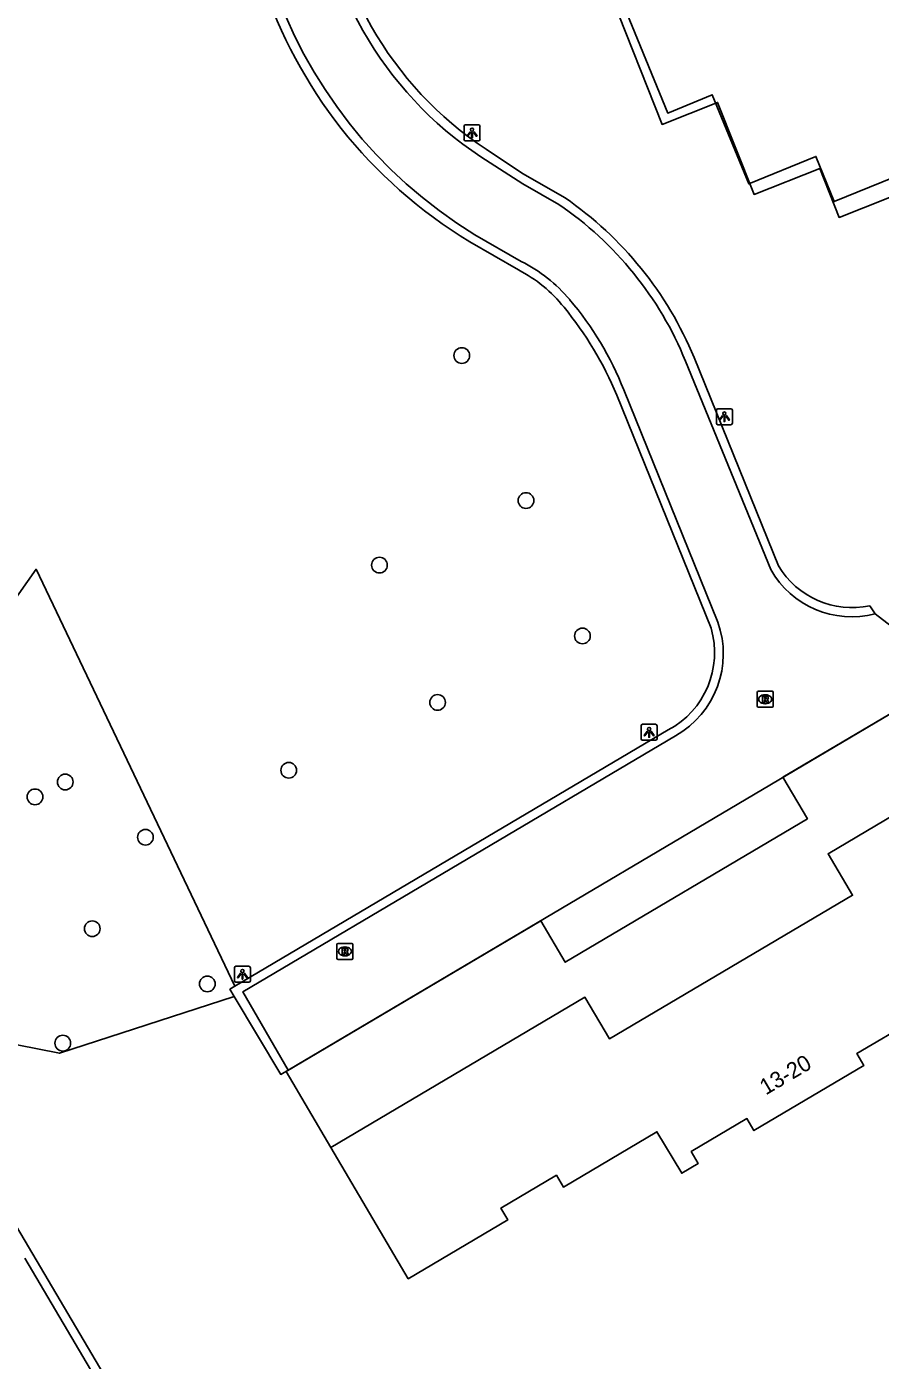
# Model space of a CAD drawing. Extents: x 156664 to 157568, y 383571 to 384421.
# Drawn here: x 156750.4 to 156803.6, y 383749.5 to 383832.6 of the extents above; entities that cross this region are included whole.
import ezdxf

# ---------------------------------------------------------------- set-up
doc = ezdxf.new("R2010")
doc.units = 0
for name, color, linetype in [('IMGEO_Boom', 7, 'Continuous'), ('IMGEO_Groenvoorziening', 7, 'Continuous'), ('IMGEO_Lichtpunt', 7, 'Continuous'), ('IMGEO_Pand', 7, 'Continuous'), ('IMGEO_Pand_nummerreeks', 7, 'Continuous'), ('IMGEO_Pand_overbouw', 7, 'Continuous'), ('IMGEO_Pand_vergunning_verleend', 7, 'Continuous'), ('IMGEO_Rijbaan_lokaal_gesloten', 7, 'Continuous'), ('IMGEO_Rijbaan_lokaal_halfverhard', 7, 'Continuous'), ('IMGEO_Rijbaan_lokaal_open', 7, 'Continuous'), ('IMGEO_Rioolput', 7, 'Continuous')]:
    doc.layers.add(name, color=color, linetype=linetype)

msp = doc.modelspace()

# ---------------------------------------------------------------- linework, layer by layer
at = {"layer": 'IMGEO_Boom'}
for centre in [(156777.531, 383812.095), (156781.531, 383803.065), (156772.399, 383799.045), (156785.049, 383794.635), (156776.021, 383790.495), (156766.747, 383786.271), (156752.817, 383785.542), (156750.932, 383784.616), (156757.815, 383782.1), (156754.501, 383776.407), (156761.671, 383772.969), (156752.666, 383769.281)]:
    msp.add_circle(centre, 0.489, dxfattribs=at)
at = {"layer": 'IMGEO_Groenvoorziening'}
msp.add_lwpolyline([(156763.35, 383772.193), (156752.452, 383768.65), (156744.519, 383770.221), (156737.487, 383779.603), (156751.004, 383798.789), (156763.392, 383772.822)], dxfattribs=at)
at = {"layer": 'IMGEO_Lichtpunt'}
for p, q in [((156777.668, 383826.364), (156777.668, 383825.557)), ((156777.668, 383826.364), (156777.668, 383825.557)), ((156778.57, 383826.459), (156777.762, 383826.459)), ((156778.57, 383826.459), (156777.762, 383826.459)), ((156778.664, 383825.557), (156778.664, 383826.364)), ((156778.664, 383825.557), (156778.664, 383826.364)), ((156777.762, 383825.463), (156778.57, 383825.463)), ((156777.762, 383825.463), (156778.57, 383825.463)), ((156793.395, 383808.688), (156793.395, 383807.881)), ((156793.395, 383808.688), (156793.395, 383807.881)), ((156794.297, 383808.783), (156793.489, 383808.783)), ((156794.297, 383808.783), (156793.489, 383808.783)), ((156794.391, 383807.881), (156794.391, 383808.688)), ((156794.391, 383807.881), (156794.391, 383808.688)), ((156793.489, 383807.787), (156794.297, 383807.787)), ((156793.489, 383807.787), (156794.297, 383807.787)), ((156788.705, 383789.038), (156788.705, 383788.231)), ((156788.705, 383789.038), (156788.705, 383788.231)), ((156789.607, 383789.133), (156788.799, 383789.133)), ((156789.607, 383789.133), (156788.799, 383789.133)), ((156789.701, 383788.231), (156789.701, 383789.038)), ((156789.701, 383788.231), (156789.701, 383789.038)), ((156788.799, 383788.137), (156789.607, 383788.137)), ((156788.799, 383788.137), (156789.607, 383788.137)), ((156763.359, 383773.974), (156763.359, 383773.167)), ((156763.359, 383773.974), (156763.359, 383773.167)), ((156764.261, 383774.069), (156763.453, 383774.069)), ((156764.261, 383774.069), (156763.453, 383774.069)), ((156764.355, 383773.167), (156764.355, 383773.974)), ((156764.355, 383773.167), (156764.355, 383773.974)), ((156763.453, 383773.073), (156764.261, 383773.073)), ((156763.453, 383773.073), (156764.261, 383773.073))]:
    msp.add_line(p, q, dxfattribs=at)
for points in [[(156778.042, 383826.028), (156778.081, 383826), (156777.893, 383825.738), (156777.855, 383825.765), (156778.042, 383826.028)], [(156778.144, 383825.98), (156778.191, 383825.98), (156778.191, 383825.658), (156778.144, 383825.658), (156778.144, 383825.98)], [(156778.254, 383826), (156778.292, 383826.027), (156778.479, 383825.765), (156778.44, 383825.737), (156778.254, 383826)], [(156793.769, 383808.352), (156793.808, 383808.324), (156793.62, 383808.062), (156793.582, 383808.089), (156793.769, 383808.352)], [(156793.871, 383808.304), (156793.918, 383808.304), (156793.918, 383807.982), (156793.871, 383807.982), (156793.871, 383808.304)], [(156793.981, 383808.324), (156794.019, 383808.351), (156794.206, 383808.089), (156794.167, 383808.061), (156793.981, 383808.324)], [(156789.079, 383788.702), (156789.118, 383788.674), (156788.93, 383788.412), (156788.892, 383788.439), (156789.079, 383788.702)], [(156789.181, 383788.654), (156789.228, 383788.654), (156789.228, 383788.332), (156789.181, 383788.332), (156789.181, 383788.654)], [(156789.291, 383788.674), (156789.329, 383788.701), (156789.516, 383788.439), (156789.477, 383788.411), (156789.291, 383788.674)], [(156763.733, 383773.638), (156763.772, 383773.61), (156763.584, 383773.348), (156763.546, 383773.375), (156763.733, 383773.638)], [(156763.835, 383773.59), (156763.882, 383773.59), (156763.882, 383773.268), (156763.835, 383773.268), (156763.835, 383773.59)], [(156763.945, 383773.61), (156763.983, 383773.637), (156764.17, 383773.375), (156764.131, 383773.347), (156763.945, 383773.61)]]:
    msp.add_lwpolyline(points, dxfattribs=at)
for centre in [(156778.167, 383826.162), (156793.894, 383808.486), (156789.204, 383788.836), (156763.858, 383773.772)]:
    msp.add_circle(centre, 0.0994, dxfattribs=at)
for centre, start, end in [((156777.762, 383826.364), 90, 180), ((156777.762, 383826.364), 90, 180), ((156778.57, 383826.364), 0, 90), ((156778.57, 383826.364), 0, 90), ((156777.762, 383825.557), 180, 270), ((156777.762, 383825.557), 180, 270), ((156778.57, 383825.557), 270, 0), ((156778.57, 383825.557), 270, 360), ((156793.489, 383808.688), 90, 180), ((156793.489, 383808.688), 90, 180), ((156794.297, 383808.688), 0, 90), ((156794.297, 383808.688), 0, 90), ((156793.489, 383807.881), 180, 270), ((156793.489, 383807.881), 180, 270), ((156794.297, 383807.881), 270, 0), ((156794.297, 383807.881), 270, 360), ((156788.799, 383789.038), 90, 180), ((156788.799, 383789.038), 90, 180), ((156789.607, 383789.038), 0, 90), ((156789.607, 383789.038), 0, 90), ((156788.799, 383788.231), 180, 270), ((156788.799, 383788.231), 180, 270), ((156789.607, 383788.231), 270, 0), ((156789.607, 383788.231), 270, 360), ((156763.453, 383773.974), 90, 180), ((156763.453, 383773.974), 90, 180), ((156764.261, 383773.974), 0, 90), ((156764.261, 383773.974), 0, 90), ((156763.453, 383773.167), 180, 270), ((156763.453, 383773.167), 180, 270), ((156764.261, 383773.167), 270, 0), ((156764.261, 383773.167), 270, 360)]:
    msp.add_arc(centre, 0.0946, start, end, dxfattribs=at)
at = {"layer": 'IMGEO_Pand'}
for points in [[(156807.966, 383825.04), (156808.116, 383824.67), (156800.741, 383821.682), (156799.598, 383824.496), (156795.415, 383822.785), (156793.137, 383828.33), (156790.362, 383827.188), (156787.627, 383833.862), (156788.459, 383834.206), (156786.933, 383837.925), (156786.103, 383837.581), (156783.375, 383844.241), (156784.761, 383844.813), (156780.2, 383855.943), (156794.056, 383861.612), (156795.923, 383862.376), (156798.209, 383863.311), (156804.039, 383865.696)], [(156805.608, 383770.675), (156802.142, 383768.636), (156802.59, 383767.89), (156795.733, 383763.84), (156795.294, 383764.582), (156791.83, 383762.532), (156792.267, 383761.792), (156791.238, 383761.184), (156789.694, 383763.767), (156783.863, 383760.324), (156783.43, 383761.054), (156779.966, 383759.014), (156780.395, 383758.276), (156774.198, 383754.617), (156769.377, 383762.774), (156785.206, 383772.136), (156786.73, 383769.552), (156801.885, 383778.489), (156800.361, 383781.074), (156811.074, 383787.411)]]:
    msp.add_lwpolyline(points, dxfattribs=at)
at = {"layer": 'IMGEO_Pand_overbouw'}
msp.add_lwpolyline([(156808.267, 383792.167), (156797.545, 383785.836), (156799.072, 383783.25), (156783.979, 383774.316), (156782.465, 383776.905), (156766.577, 383767.511), (156769.377, 383762.774), (156785.206, 383772.136), (156786.73, 383769.552), (156801.885, 383778.489), (156800.361, 383781.074), (156811.074, 383787.411)], close=True, dxfattribs=at)
at = {"layer": 'IMGEO_Pand_vergunning_verleend'}
msp.add_lwpolyline([(156780.469, 383854.207), (156810.422, 383866.069), (156813.706, 383857.943), (156816.747, 383859.147), (156823.563, 383841.936), (156820.432, 383840.696), (156822.305, 383835.967), (156820.454, 383835.234), (156822.799, 383829.314), (156801.042, 383820.698), (156799.834, 383823.747), (156795.744, 383822.127), (156793.475, 383827.857), (156790.011, 383826.485), (156783.663, 383842.517), (156784.904, 383843.008), (156780.469, 383854.207)], dxfattribs=at)
at = {"layer": 'IMGEO_Rijbaan_lokaal_gesloten'}
for points in [[(156783.963, 383821.909), (156781.318, 383823.436), (156779.043, 383824.936)], [(156778.718, 383824.465), (156781.34, 383822.787), (156783.574, 383821.503)], [(156781.058, 383817.423), (156778.021, 383819.184)], [(156778.347, 383819.615), (156781.238, 383817.955)], [(156791.468, 383811.752), (156796.785, 383798.775)], [(156797.264, 383799.006), (156792.007, 383811.962)], [(156787.626, 383809.956), (156793.479, 383795.501)], [(156793.061, 383795.116), (156787.182, 383809.636)], [(156803.286, 383796.013), (156802.956, 383796.509)], [(156763.392, 383772.822), (156790.393, 383788.783)], [(156790.845, 383788.423), (156763.879, 383772.471), (156766.719, 383767.595)], [(156763.392, 383772.822), (156763.084, 383772.64), (156763.35, 383772.193)], [(156766.719, 383767.595), (156766.247, 383767.332), (156763.35, 383772.193)]]:
    msp.add_lwpolyline(points, dxfattribs=at)
for centre, radius, start, end in [((156791.351, 383843.635), 22.958, 128.2084, 236.61447), ((156791.42, 383843.662), 22.447, 128.87084, 236.53772), ((156793.467, 383844.757), 29.876, 157.83284, 238.86903), ((156793.864, 383844.982), 29.736, 158.50885, 238.54582), ((156771.164, 383803.333), 22.559, 22.49043, 55.43354), ((156771.39, 383803.568), 21.682, 22.17535, 55.809), ((156777.125, 383809.711), 8.657, 38.49853, 62.97757), ((156776.877, 383809.328), 9.667, 40.26713, 63.18213), ((156767.174, 383801.336), 21.661, 22.53107, 39.45194), ((156768.931, 383802.558), 20.105, 21.58981, 40.3527), ((156801.831, 383801.62), 5.793, 209.41518, 284.54765), ((156801.864, 383801.756), 5.36, 210.87491, 281.75233), ((156787.836, 383793.589), 5.444, 298.01823, 16.29181), ((156787.98, 383793.518), 5.846, 299.34857, 19.82703)]:
    msp.add_arc(centre, radius, start, end, dxfattribs=at)
at = {"layer": 'IMGEO_Rijbaan_lokaal_halfverhard'}
msp.add_lwpolyline([(156734.042, 383784.492), (156785.456, 383697.466)], dxfattribs=at)
at = {"layer": 'IMGEO_Rijbaan_lokaal_open'}
for points in [[(156803.286, 383796.013), (156808.279, 383792.181), (156766.719, 383767.595)], [(156784.956, 383697.199), (156750.297, 383755.891)]]:
    msp.add_lwpolyline(points, dxfattribs=at)
at = {"layer": 'IMGEO_Rioolput'}
for p, q in [((156795.937, 383790.27), (156795.937, 383791.122)), ((156796.012, 383791.196), (156796.864, 383791.196)), ((156796.425, 383790.976), (156796.45, 383790.976)), ((156796.938, 383791.122), (156796.938, 383790.27)), ((156796.864, 383790.196), (156796.012, 383790.196)), ((156796.448, 383790.416), (156796.423, 383790.416)), ((156769.745, 383774.569), (156769.745, 383775.421)), ((156769.82, 383775.495), (156770.672, 383775.495)), ((156770.233, 383775.275), (156770.258, 383775.275)), ((156770.746, 383775.421), (156770.746, 383774.569)), ((156770.672, 383774.495), (156769.82, 383774.495)), ((156770.256, 383774.715), (156770.231, 383774.715))]:
    msp.add_line(p, q, dxfattribs=at)
for points in [[(156795.937, 383790.27), (156795.937, 383791.122)], [(156796.012, 383791.196), (156796.864, 383791.196)], [(156796.526, 383790.894), (156796.274, 383790.896), (156796.274, 383790.496)], [(156796.938, 383791.122), (156796.938, 383790.27)], [(156796.864, 383790.196), (156796.012, 383790.196)], [(156796.274, 383790.496), (156796.398, 383790.496), (156796.398, 383790.658), (156796.409, 383790.658)], [(156796.452, 383790.815), (156796.398, 383790.815), (156796.398, 383790.734)], [(156796.398, 383790.734), (156796.45, 383790.734)], [(156796.456, 383790.629), (156796.527, 383790.496), (156796.667, 383790.496), (156796.602, 383790.622)], [(156769.745, 383774.569), (156769.745, 383775.421)], [(156769.82, 383775.495), (156770.672, 383775.495)], [(156770.334, 383775.193), (156770.082, 383775.195), (156770.082, 383774.795)], [(156770.26, 383775.114), (156770.206, 383775.114), (156770.206, 383775.033)], [(156770.746, 383775.421), (156770.746, 383774.569)], [(156770.672, 383774.495), (156769.82, 383774.495)], [(156770.082, 383774.795), (156770.206, 383774.795), (156770.206, 383774.957), (156770.217, 383774.957)], [(156770.206, 383775.033), (156770.258, 383775.033)], [(156770.264, 383774.928), (156770.335, 383774.795), (156770.475, 383774.795), (156770.41, 383774.921)]]:
    msp.add_lwpolyline(points, dxfattribs=at)
for centre, radius, start, end in [((156796.014, 383791.12), 0.0765, 91.55205, 178.44795), ((156796.014, 383791.12), 0.0765, 91.55205, 178.44795), ((156796.525, 383790.784), 0.109, 350.36119, 89.41601), ((156796.862, 383791.12), 0.0765, 1.55205, 88.44795), ((156796.862, 383791.12), 0.0765, 1.55205, 88.44795), ((156796.014, 383790.272), 0.0765, 181.55205, 268.44795), ((156796.014, 383790.272), 0.0765, 181.55205, 268.44795), ((156796.408, 383790.605), 0.0533, 26.02933, 88.69889), ((156796.434, 383790.923), 0.19, 274.7715, 282.96867), ((156796.458, 383790.719), 0.0964, 77.00612, 93.18647), ((156796.472, 383790.776), 0.0378, 276.66336, 79.67722), ((156796.523, 383790.784), 0.112, 277.58423, 350.98172), ((156796.507, 383790.569), 0.108, 29.51342, 73.79051), ((156796.862, 383790.272), 0.0765, 271.55205, 358.44795), ((156796.862, 383790.272), 0.0765, 271.55205, 358.44795), ((156769.822, 383775.419), 0.0765, 91.55205, 178.44795), ((156769.822, 383775.419), 0.0765, 91.55205, 178.44795), ((156770.266, 383775.018), 0.0964, 77.00612, 93.18647), ((156770.28, 383775.075), 0.0378, 276.66336, 79.67722), ((156770.333, 383775.083), 0.109, 350.36119, 89.41601), ((156770.331, 383775.083), 0.112, 277.58423, 350.98172), ((156770.67, 383775.419), 0.0765, 1.55205, 88.44795), ((156770.67, 383775.419), 0.0765, 1.55205, 88.44795), ((156769.822, 383774.571), 0.0765, 181.55205, 268.44795), ((156769.822, 383774.571), 0.0765, 181.55205, 268.44795), ((156770.216, 383774.904), 0.0533, 26.02933, 88.69889), ((156770.242, 383775.222), 0.19, 274.7715, 282.96867), ((156770.315, 383774.868), 0.108, 29.51342, 73.79051), ((156770.67, 383774.571), 0.0765, 271.55205, 358.44795), ((156770.67, 383774.571), 0.0765, 271.55205, 358.44795)]:
    msp.add_arc(centre, radius, start, end, dxfattribs=at)
for centre, major_axis, ratio, start_param, end_param in [((156796.424, 383790.696), (-0.387, 0.002), 0.722429, 4.712389, 7.853982), ((156796.449, 383790.696), (-0.39, 0.002), 0.717154, 1.570796, 4.712389), ((156770.232, 383774.995), (-0.387, 0.002), 0.722429, 4.712389, 7.853982), ((156770.257, 383774.995), (-0.39, 0.002), 0.717154, 1.570796, 4.712389)]:
    msp.add_ellipse(centre, major_axis=major_axis, ratio=ratio, start_param=start_param, end_param=end_param, dxfattribs=at)

# ---------------------------------------------------------------- texts
at = {"layer": 'IMGEO_Pand_nummerreeks'}
msp.add_text('13-20', height=1, rotation=30.5673, dxfattribs=at).set_placement((156796.475, 383766.021))

doc.saveas('drawing.dxf')
